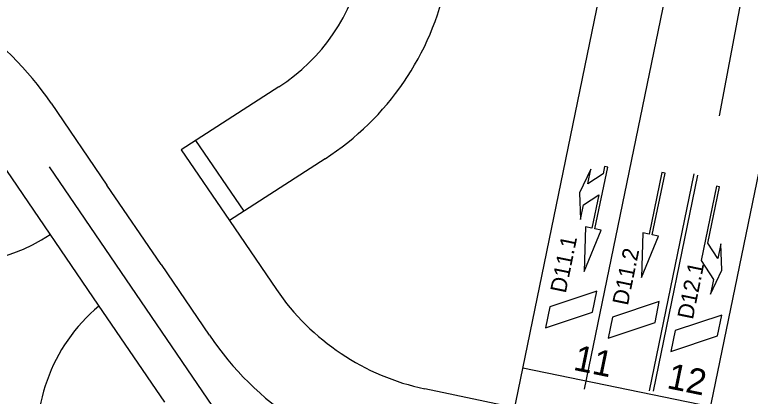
# Model space of a CAD drawing. Extents: x 81065 to 81486, y 452384 to 452681.
# Drawn here: x 81198.69 to 81233.14, y 452554.16 to 452572.01 of the extents above; entities that cross this region are included whole.
import ezdxf

# ---------------------------------------------------------------- set-up
doc = ezdxf.new("R2010")
doc.units = 0
for name, color, linetype in [('B-BH-VH-KANTOPSLUITING-GV', 7, 'Continuous'), ('B-WE-VW-MARKERING_DWARS_STOPSTREEP_030-G', 7, 'Continuous'), ('B-WE-VW-MARKERING_LANGS_STREEP_13_010-G', 7, 'Continuous'), ('B-WE-VW-MARKERING_LANGS_STREEP_13_030-G', 7, 'Continuous'), ('B-WE-VW-MARKERING_LANGS_STREEP_30270_010-G', 7, 'Continuous'), ('B-WE-VW-MARKERING_LANGS_STREEP_DOORGETROKKEN_010-G', 7, 'Continuous'), ('B-WE-VW-MARKERING_PIJL-S', 7, 'Continuous'), ('N-OI-KL-VRI_LUS_DETECTIE-G', 7, 'Continuous'), ('N-OI-KL-VRI_LUS_DETECTIE-T18', 7, 'Continuous'), ('N-WE-VW-VRI_RICHTINGNUMMER-T25', 7, 'Continuous')]:
    doc.layers.add(name, color=color, linetype=linetype)

msp = doc.modelspace()

# ---------------------------------------------------------------- linework, layer by layer
at = {"layer": 'B-BH-VH-KANTOPSLUITING-GV'}
for p, q in [((81221.337, 452549.903), (81232.532, 452604.152)), ((81230.235, 452548.568), (81237.12, 452582.041)), ((81211.058, 452568.634), (81206.484, 452565.686)), ((81200.398, 452567.863), (81203.008, 452564.039)), ((81207.157, 452566.119), (81209.413, 452562.814)), ((81206.484, 452565.686), (81208.74, 452562.38)), ((81213.225, 452565.272), (81208.74, 452562.38)), ((81198.304, 452564.722), (81202.602, 452558.424)), ((81205.545, 452560.321), (81203.008, 452564.039)), ((81208.74, 452562.38), (81210.942, 452559.154)), ((81205.545, 452560.321), (81207.803, 452557.012)), ((81202.602, 452558.424), (81205.707, 452553.875)), ((81222.116, 452553.622), (81217.899, 452554.505))]:
    msp.add_line(p, q, dxfattribs=at)
for centre, radius, start, end in [((81188.008, 452559.407), 15, 34.3113, 78.2967), ((81206.182, 452576.198), 9, 302.8079, 348.3405), ((81206.182, 452576.198), 13, 302.8079, 348.3405), ((81195.871, 452568.362), 8, 249.7756, 304.0114), ((81220.193, 452565.467), 11.2, 214.3113, 258.1811), ((81207.74, 452552.218), 8, 129.6581, 191.1796), ((81220.193, 452565.467), 15, 214.3113, 258.1811)]:
    msp.add_arc(centre, radius, start, end, dxfattribs=at)
at = {"layer": 'B-WE-VW-MARKERING_DWARS_STOPSTREEP_030-G'}
msp.add_line((81222.489, 452555.483), (81231.285, 452553.673), dxfattribs=at)
at = {"layer": 'B-WE-VW-MARKERING_LANGS_STREEP_13_010-G'}
msp.add_line((81234.813, 452600.381), (81225.36, 452554.492), dxfattribs=at)
at = {"layer": 'B-WE-VW-MARKERING_LANGS_STREEP_13_030-G'}
msp.add_line((81231.691, 452567.281), (81238.216, 452601.793), dxfattribs=at)
at = {"layer": 'B-WE-VW-MARKERING_LANGS_STREEP_30270_010-G'}
msp.add_line((81200.309, 452564.888), (81208.516, 452552.863), dxfattribs=at)
at = {"layer": 'B-WE-VW-MARKERING_LANGS_STREEP_DOORGETROKKEN_010-G'}
for p, q in [((81228.421, 452554.416), (81230.51, 452564.559)), ((81228.607, 452554.4), (81230.688, 452564.501))]:
    msp.add_line(p, q, dxfattribs=at)
at = {"layer": 'B-WE-VW-MARKERING_PIJL-S'}
for p, q in [((81225.676, 452564.783), (81225.137, 452563.67)), ((81225.533, 452564.098), (81225.676, 452564.783)), ((81225.859, 452561.987), (81226.462, 452564.875)), ((81226.315, 452564.906), (81226.243, 452564.563)), ((81226.462, 452564.875), (81226.315, 452564.906)), ((81226.243, 452564.563), (81225.533, 452564.098)), ((81231.558, 452563.986), (81230.832, 452560.511)), ((81231.153, 452561.312), (81231.704, 452563.955)), ((81231.704, 452563.955), (81231.558, 452563.986)), ((81225.137, 452563.67), (81225.186, 452562.434)), ((81225.329, 452563.119), (81226.039, 452563.584)), ((81226.039, 452563.584), (81225.712, 452562.018)), ((81225.186, 452562.434), (81225.329, 452563.119)), ((81225.418, 452562.079), (81225.366, 452559.996)), ((81225.712, 452562.018), (81225.418, 452562.079)), ((81225.366, 452559.996), (81226.152, 452561.926)), ((81226.152, 452561.926), (81225.859, 452561.987)), ((81231.617, 452560.602), (81231.153, 452561.312)), ((81231.76, 452561.287), (81231.617, 452560.602)), ((81231.809, 452560.051), (81231.76, 452561.287)), ((81230.832, 452560.511), (81231.413, 452559.623)), ((81231.27, 452558.938), (81231.809, 452560.051)), ((81231.413, 452559.623), (81231.27, 452558.938))]:
    msp.add_line(p, q, dxfattribs=at)
msp.add_lwpolyline([(81228.05, 452559.719), (81228.836, 452561.649), (81228.543, 452561.711), (81229.145, 452564.599), (81228.999, 452564.629), (81228.396, 452561.741), (81228.102, 452561.803)], close=True, dxfattribs=at)
at = {"layer": 'N-OI-KL-VRI_LUS_DETECTIE-G'}
for p, q in [((81225.945, 452559.068), (81223.755, 452558.337)), ((81225.746, 452558.088), (81225.945, 452559.068)), ((81228.876, 452558.584), (81226.686, 452557.853)), ((81228.676, 452557.604), (81228.876, 452558.584)), ((81223.755, 452558.337), (81223.555, 452557.358)), ((81223.555, 452557.358), (81225.746, 452558.088)), ((81231.808, 452557.957), (81229.618, 452557.226)), ((81231.608, 452556.977), (81231.808, 452557.957)), ((81226.686, 452557.853), (81226.486, 452556.874)), ((81226.486, 452556.874), (81228.676, 452557.604)), ((81229.618, 452557.226), (81229.418, 452556.247)), ((81229.418, 452556.247), (81231.608, 452556.977))]:
    msp.add_line(p, q, dxfattribs=at)

# ---------------------------------------------------------------- texts
at = {"layer": 'N-OI-KL-VRI_LUS_DETECTIE-T18'}
for s, p in [('D11.1', (81224.494, 452558.948)), ('D11.2', (81227.404, 452558.372)), ('D12.1', (81230.447, 452557.717))]:
    msp.add_text(s, height=0.75, rotation=78.3917, dxfattribs=at).set_placement(p)
at = {"layer": 'N-WE-VW-VRI_RICHTINGNUMMER-T25'}
for s, p in [('11', (81224.804, 452555.399)), ('12', (81229.186, 452554.545))]:
    msp.add_text(s, height=1.2, rotation=348.375, dxfattribs=at).set_placement(p)

doc.saveas('drawing.dxf')
